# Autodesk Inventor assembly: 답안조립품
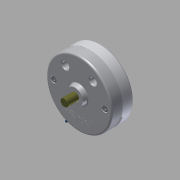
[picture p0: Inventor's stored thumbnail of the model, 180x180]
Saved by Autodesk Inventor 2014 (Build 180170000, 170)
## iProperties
Created: 2015-06
Part Number: 답안조립품
Document SubType Name: Assembly
Designer: MYHOME
Author: MYHOME
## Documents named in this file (10)
- C:\Documents and Settings\MYHOME\바탕 화면\450631V1031\답안조립품.iam
- C:\Documents and Settings\MYHOME\바탕 화면\450631V1031\본체.ipt
- C:\Documents and Settings\MYHOME\바탕 화면\450631V1031\덮개.ipt
- C:\Documents and Settings\MYHOME\바탕 화면\450631V1031\베어링62_22.ipt
- C:\Documents and Settings\MYHOME\바탕 화면\450631V1031\축.ipt
- C:\Documents and Settings\MYHOME\바탕 화면\450631V1031\멈춤링.ipt
- C:\Documents and Settings\MYHOME\바탕 화면\450631V1031\슬라이더2.ipt
- C:\Documents and Settings\MYHOME\바탕 화면\450631V1031\슬라이더.ipt
- C:\Documents and Settings\MYHOME\바탕 화면\450631V1031\평행핀.ipt
- C:\Documents and Settings\MYHOME\바탕 화면\450631V1031\M10x35.ipt
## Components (7 placed, 4 different names)
1. KS B 2023 62/22 - 22 x 50 x 14:1 — 각도:3
2. KS B 1336 22 x 1.2:1 — 각도:1
3. KS B 1336 22 x 1.2:2 — 각도:4
4. KS B 2023 62/22 - 22 x 50 x 14:2 — 각도:5
5. KS B 1320 B B 5 x  20:1
6. KS B 1003 - 미터 M 10 x 35:1
7. KS B 1003 - 미터 M 10 x 35:2
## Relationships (4: Angle 4)
- 각도:1 [Angle]: KS B 1336 22 x 1.2:1
- 각도:3 [Angle]: KS B 2023 62/22 - 22 x 50 x 14:1
- 각도:4 [Angle]: KS B 1336 22 x 1.2:2
- 각도:5 [Angle]: KS B 2023 62/22 - 22 x 50 x 14:2
